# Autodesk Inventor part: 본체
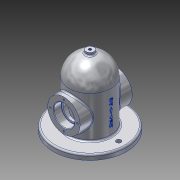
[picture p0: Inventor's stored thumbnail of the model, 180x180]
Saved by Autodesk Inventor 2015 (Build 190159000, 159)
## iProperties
Created: 2019-11
Part Number: 본체
Material: 알루미늄 6061
Document SubType Name: Modeling
Designer: LINEART-SSD.D4.16.04
Density: 2.7 g/cm^3
Appearance: 알루미늄 - 평지
Mass: 1106.19 g
Surface Area: 884.499 cm^2
Volume: 409.7 cm^3
Author: LINEART-SSD.D4.16.04
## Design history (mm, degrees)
sketch "스케치1"
  geometry: C1 r 70 at (0, 0); 1 further point
  constraints: 1 centre point, 1 coincident
  dimensions: "d0" = 140 diameter of C1
extrude "돌출1" new body sketch "스케치1" distance "d1" = 10; taper "d2" = 0 deg
fillet "모깎기1" dims "d3" = 3
sketch "스케치2"
  geometry: C1 r 40 at (0, 0); 1 further point
  constraints: 1 centre point, 1 coincident
  dimensions: "d4" = 80 diameter of C1
extrude "돌출2" join sketch "스케치2" distance "d5" = 80; taper "d6" = 0 deg
sketch "스케치3"
  geometry: L1 (90, -40)-(90, 40) reference; L2 (0, 0)-(130, 0); L3 (90, 0)-(90, -40); A1 r 40 centre (90, 0) between (90, -40) and (130, 0)
  constraints: 5 end point, 2 point on circle, 1 centre point, 1 horizontal, 1 midpoint, 1 point on line, 1 vertical
revolve "회전1" sketch "스케치3" stored, may be unused: angle "d8" = 90 deg
sketch "스케치4"
  geometry: L1 (123.682, 0)-(135, 0); L2 (123.682, -7.5)-(135, -7.5) reference; L3 (123.682, 7)-(135, 7); L4 (135, 7)-(135, -7.5); L5 (0, 70)-(0, -70) reference; L6 (123.682, 7)-(123.682, -7.5); A1 r 40 centre (90, 0) between (90, -40) and (90, 40) reference; 1 further point
  constraints: 10 end point, 2 horizontal, 2 parallel, 2 point on line, 1 perpendicular, 1 vertical
  dimensions: "d9" = 7.5 distance between parallel lines of L1 L2; "d10" = 7 distance between parallel lines of L1 L3; "d11" = 135 distance between parallel lines of L5 L4; "d12" = 123.68236 distance between parallel lines of L5 L6
revolve "회전2" sketch "스케치4" stored, may be unused: angle "d13" = 90 deg
node "작업 평면1"
sketch "스케치5"
  geometry: L1 (-10, 70)-(-10, -70) reference; 3 further points
  constraints: 1 horizontal alignment, 1 midpoint, 1 other
  dimensions: "d14" = 50 distance from line of L1 point (40, 0)
feature "엠보싱1" sketch "스케치5" dims "d15" = 1, "d16" = 0
sketch "스케치6"
  geometry: L1 (-70, 0)-(70, 0) reference; C1 r 31 at (0, 50); 1 further point
  constraints: 1 centre point
  dimensions: "d17" = 62 diameter of C1; "d18" = 50 distance from line of L1 C1.centre; "d19" = 70 horizontal distance of L1.start C1.centre
extrude "돌출3" join sketch "스케치6" stored distance "d20" = 100; taper "d21" = 0 deg
sketch "스케치7"
  geometry: L1 (-70, -50)-(70, -50) reference; C1 r 20 at (0, 0); 1 further point
  constraints: 1 centre point
  dimensions: "d22" = 40 diameter of C1; "d23" = 50 distance from line of L1 C1.centre; "d24" = 70 horizontal distance of L1.start C1.centre
extrude "돌출4" cut sketch "스케치7" distance "d25" = 15; taper "d26" = 0 deg
chamfer "모따기1" distance "d27" = 1; stored, may be unused: second distance "d28" = 2, angle "d29" = 45 deg
fillet "모깎기2" dims "d30" = 0.3
sketch "스케치8"
  geometry: L1 (-70, -50)-(70, -50) reference; C1 r 16.5 at (0, 0); 1 further point
  constraints: 1 centre point
  dimensions: "d31" = 33 diameter of C1; "d32" = 50 distance from line of L1 C1.centre; "d33" = 70 horizontal distance of L1.start C1.centre
sketch "스케치9"
  geometry: L1 (-70, -50)-(70, -50) reference; C1 r 20 at (0, 0); 1 further point
  constraints: 1 centre point
  dimensions: "d34" = 40 diameter of C1; "d35" = 50 distance from line of L1 C1.centre; "d36" = 70 horizontal distance of L1.start C1.centre
extrude "돌출5" cut sketch "스케치9" distance "d37" = 15; taper "d38" = 0 deg
fillet "모깎기3" dims "d39" = 0.3
chamfer "모따기2" distance "d40" = 1; stored, may be unused: second distance "d41" = 2, angle "d42" = 45 deg
extrude "돌출6" cut sketch "스케치8" stored distance "d43" = 15; taper "d44" = 0 deg
sketch "스케치10"
  geometry: L1 (0, -30)-(90, -30) reference; L2 (90, -30)-(90, 0) reference; L3 (0, 0)-(0, -30); L4 (120, 0)-(0, 0) reference; A1 r 30 centre (90, 0) between (90, -30) and (120, 0)
  constraints: 8 end point, 3 horizontal, 2 point on circle, 2 point on line, 1 centre point, 1 perpendicular, 1 vertical, 1 other
  dimensions: "d48" = 30 radius of A1; "d49" = 30 distance of L3.start L1.start; "d50" = 90 distance of L1.start L1.end
revolve "회전3" sketch "스케치10" stored, may be unused: angle "d51" = 90 deg
hole "구멍1" diameter "d54" = 5.188; stored, may be unused: countersink angle "d58" = 90 deg, drill point angle "d60" = 118 deg; dims "d52" = 10, "d53" = 10, "d55" = 12, "d56" = 4, "d57" = 2, "d59" = 16
sketch "스케치11"
  geometry: L1 (-70, -50)-(70, -50) reference; A1 r 26 centre (0, 0) between (0, 26) and (0, -26); 3 further points
  constraints: 4 point on circle, 1 centre point, 2 other
  dimensions: "d61" = 52 diameter of A1; "d62" = 52 distance of point (-26, 0) point (26, 0); "d63" = 50 distance from line of L1 point (-26, 0)
hole "구멍2" sketch "스케치11" at (0, 26), (0, -26), (26, 0), (-26, 0) diameter "d64" = 3.242; stored, may be unused: countersink angle "d68" = 90 deg, drill point angle "d70" = 118 deg; dims "d65" = 8, "d66" = 4, "d67" = 2, "d69" = 10
fillet "모깎기4" dims "d71" = 3
fillet "모깎기5" dims "d72" = 3
sketch "스케치12"
  geometry: C1 r 2.594 at (0, 0) reference; A1 r 55 centre (0, 0) between (-55, 0) and (55, 0) reference; 1 further point
  constraints: 2 point on circle, 1 centre point, 1 coincident, 2 other
  dimensions: "d74" = 110 distance of A1.start A1.end
hole "구멍3" sketch "스케치12" at (-55, 0), (55, 0) diameter "d75" = 9; stored, may be unused: countersink angle "d79" = 90 deg, drill point angle "d81" = 0 deg; dims "d76" = 8, "d77" = 4, "d78" = 2, "d80" = 10
node "솔리드1"
mirror "대칭1"
